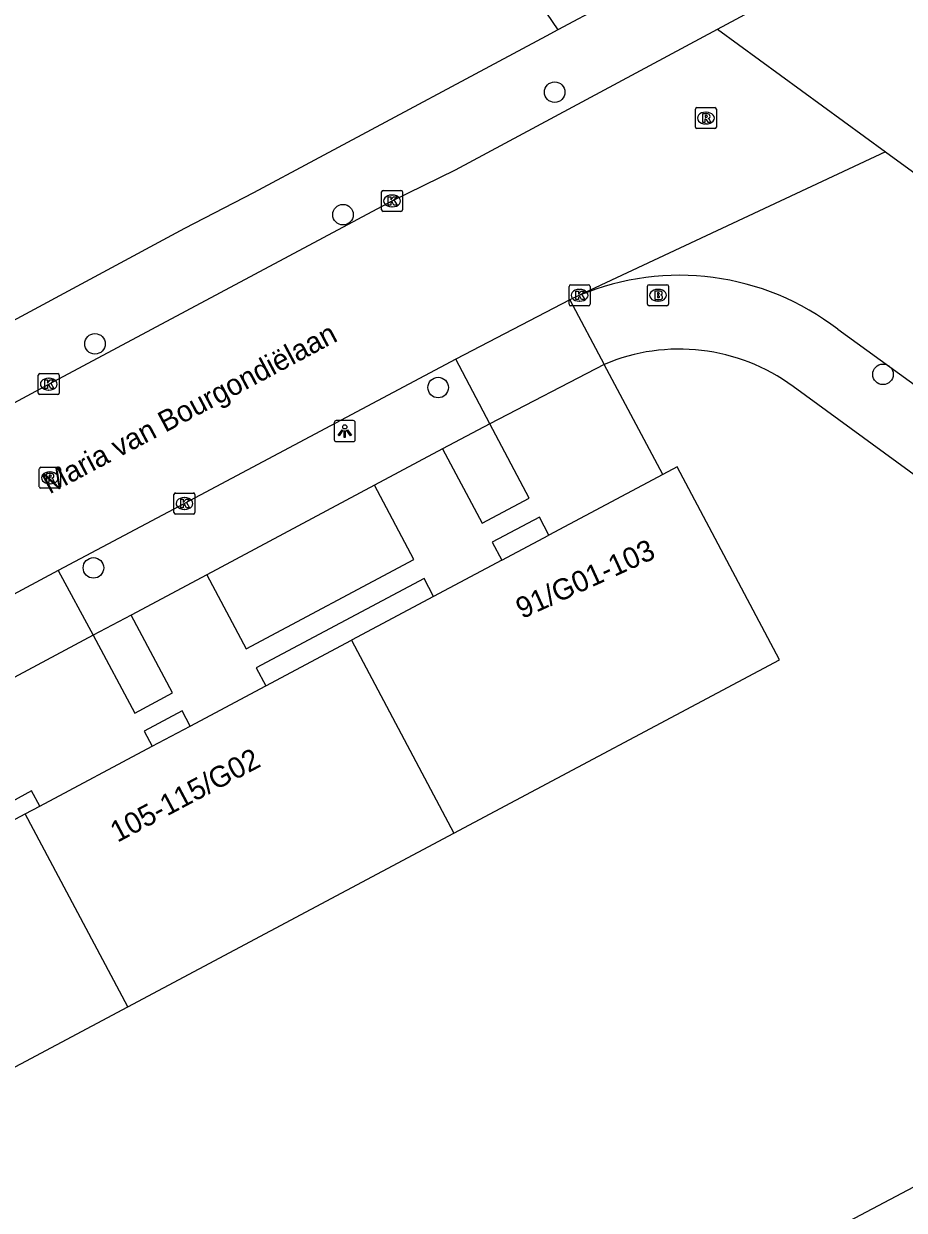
# Model space of a CAD drawing. Extents: x 159675 to 160530, y 382179 to 382901.
# Drawn here: x 159930.6 to 159972.5, y 382360.9 to 382417.3 of the extents above; entities that cross this region are included whole.
import ezdxf

# ---------------------------------------------------------------- set-up
doc = ezdxf.new("R2010")
doc.units = 0
for name, color, linetype in [('IMGEO_Boom', 7, 'Continuous'), ('IMGEO_Brandkraan', 7, 'Continuous'), ('IMGEO_Kolk', 7, 'Continuous'), ('IMGEO_Lichtpunt', 7, 'Continuous'), ('IMGEO_Openbare_ruimte_label', 7, 'Continuous'), ('IMGEO_Pand', 7, 'Continuous'), ('IMGEO_Pand_nummerreeks', 7, 'Continuous'), ('IMGEO_Rijbaan_lokaal_gesloten', 7, 'Continuous'), ('IMGEO_Rijbaan_lokaal_open', 7, 'Continuous'), ('IMGEO_Rioolput', 7, 'Continuous'), ('IMGEO_Voetpad_open', 7, 'Continuous')]:
    doc.layers.add(name, color=color, linetype=linetype)

msp = doc.modelspace()

# ---------------------------------------------------------------- linework, layer by layer
at = {"layer": 'IMGEO_Boom'}
for centre in [(159955.841, 382414.081), (159945.764, 382408.25), (159933.952, 382402.106), (159971.473, 382400.653), (159950.292, 382400.025), (159933.879, 382391.445)]:
    msp.add_circle(centre, 0.489, dxfattribs=at)
at = {"layer": 'IMGEO_Brandkraan'}
for p, q in [((159960.261, 382403.991), (159960.261, 382404.843)), ((159960.336, 382404.917), (159961.188, 382404.917)), ((159960.749, 382404.697), (159960.774, 382404.697)), ((159961.262, 382404.843), (159961.262, 382403.991)), ((159961.188, 382403.917), (159960.336, 382403.917)), ((159960.772, 382404.137), (159960.747, 382404.137))]:
    msp.add_line(p, q, dxfattribs=at)
for points in [[(159960.261, 382403.991), (159960.261, 382404.843)], [(159960.336, 382404.917), (159961.188, 382404.917)], [(159960.609, 382404.617), (159960.609, 382404.217), (159960.822, 382404.217)], [(159960.84, 382404.617), (159960.609, 382404.617)], [(159960.788, 382404.536), (159960.734, 382404.536), (159960.734, 382404.46)], [(159960.734, 382404.46), (159960.787, 382404.46)], [(159961.262, 382404.843), (159961.262, 382403.991)], [(159961.188, 382403.917), (159960.336, 382403.917)], [(159960.796, 382404.384), (159960.734, 382404.384), (159960.734, 382404.303)], [(159960.734, 382404.303), (159960.796, 382404.303)]]:
    msp.add_lwpolyline(points, dxfattribs=at)
for centre, radius, start, end in [((159960.338, 382404.841), 0.0765, 91.552, 178.448), ((159960.338, 382404.841), 0.0765, 91.552, 178.448), ((159960.789, 382404.498), 0.0379, 267.8285, 90.9355), ((159960.844, 382404.472), 0.145, 59.4692, 91.5367), ((159960.869, 382404.519), 0.0922, 285.5137, 58.1501), ((159961.186, 382404.841), 0.0765, 1.552, 88.448), ((159961.186, 382404.841), 0.0765, 1.552, 88.448), ((159960.338, 382403.993), 0.0765, 181.552, 268.448), ((159960.338, 382403.993), 0.0765, 181.552, 268.448), ((159960.797, 382404.343), 0.0404, 269.8759, 90.5077), ((159960.828, 382404.468), 0.251, 268.6676, 293.5347), ((159960.874, 382404.327), 0.105, 301.3115, 78.989), ((159961.186, 382403.993), 0.0765, 271.552, 358.448), ((159961.186, 382403.993), 0.0765, 271.552, 358.448)]:
    msp.add_arc(centre, radius, start, end, dxfattribs=at)
for centre, major_axis, ratio, start_param, end_param in [((159960.748, 382404.417), (-0.387, 0.002), 0.722429, 4.712389, 7.853982), ((159960.773, 382404.417), (-0.39, 0.002), 0.717154, 1.570796, 4.712389)]:
    msp.add_ellipse(centre, major_axis=major_axis, ratio=ratio, start_param=start_param, end_param=end_param, dxfattribs=at)
at = {"layer": 'IMGEO_Kolk'}
for p, q in [((159947.596, 382408.48), (159947.596, 382409.332)), ((159947.671, 382409.406), (159948.523, 382409.406)), ((159948.084, 382409.186), (159948.109, 382409.186)), ((159948.597, 382409.332), (159948.597, 382408.48)), ((159948.523, 382408.406), (159947.671, 382408.406)), ((159948.107, 382408.626), (159948.082, 382408.626)), ((159956.526, 382403.988), (159956.526, 382404.84)), ((159956.601, 382404.914), (159957.453, 382404.914)), ((159957.014, 382404.694), (159957.039, 382404.694)), ((159957.527, 382404.84), (159957.527, 382403.988)), ((159957.453, 382403.914), (159956.601, 382403.914)), ((159957.037, 382404.134), (159957.012, 382404.134)), ((159931.251, 382399.761), (159931.251, 382400.613)), ((159931.326, 382400.687), (159932.178, 382400.687)), ((159932.252, 382400.613), (159932.252, 382399.761)), ((159931.739, 382400.467), (159931.764, 382400.467)), ((159932.178, 382399.687), (159931.326, 382399.687)), ((159931.762, 382399.907), (159931.737, 382399.907)), ((159937.713, 382394.081), (159937.713, 382394.933)), ((159937.788, 382395.007), (159938.64, 382395.007)), ((159938.714, 382394.933), (159938.714, 382394.081)), ((159938.201, 382394.787), (159938.226, 382394.787)), ((159938.64, 382394.007), (159937.788, 382394.007)), ((159938.224, 382394.227), (159938.199, 382394.227))]:
    msp.add_line(p, q, dxfattribs=at)
for points in [[(159947.596, 382408.48), (159947.596, 382409.332)], [(159947.671, 382409.406), (159948.523, 382409.406)], [(159947.917, 382409.106), (159948.04, 382409.106), (159948.04, 382408.955), (159948.17, 382409.106), (159948.334, 382409.106), (159948.188, 382408.955), (159948.341, 382408.706), (159948.189, 382408.706), (159948.104, 382408.87), (159948.04, 382408.803), (159948.04, 382408.706), (159947.917, 382408.706), (159947.917, 382409.106)], [(159948.597, 382409.332), (159948.597, 382408.48)], [(159948.523, 382408.406), (159947.671, 382408.406)], [(159956.526, 382403.988), (159956.526, 382404.84)], [(159956.601, 382404.914), (159957.453, 382404.914)], [(159956.847, 382404.614), (159956.97, 382404.614), (159956.97, 382404.463), (159957.1, 382404.614), (159957.264, 382404.614), (159957.118, 382404.463), (159957.271, 382404.214), (159957.119, 382404.214), (159957.034, 382404.378), (159956.97, 382404.311), (159956.97, 382404.214), (159956.847, 382404.214), (159956.847, 382404.614)], [(159957.527, 382404.84), (159957.527, 382403.988)], [(159957.453, 382403.914), (159956.601, 382403.914)], [(159931.251, 382399.761), (159931.251, 382400.613)], [(159931.326, 382400.687), (159932.178, 382400.687)], [(159932.252, 382400.613), (159932.252, 382399.761)], [(159931.572, 382400.387), (159931.695, 382400.387), (159931.695, 382400.236), (159931.825, 382400.387), (159931.989, 382400.387), (159931.843, 382400.236), (159931.996, 382399.987), (159931.844, 382399.987), (159931.759, 382400.151), (159931.695, 382400.084), (159931.695, 382399.987), (159931.572, 382399.987), (159931.572, 382400.387)], [(159932.178, 382399.687), (159931.326, 382399.687)], [(159937.713, 382394.081), (159937.713, 382394.933)], [(159937.788, 382395.007), (159938.64, 382395.007)], [(159938.714, 382394.933), (159938.714, 382394.081)], [(159938.034, 382394.707), (159938.157, 382394.707), (159938.157, 382394.556), (159938.287, 382394.707), (159938.451, 382394.707), (159938.305, 382394.556), (159938.458, 382394.307), (159938.306, 382394.307), (159938.221, 382394.471), (159938.157, 382394.404), (159938.157, 382394.307), (159938.034, 382394.307), (159938.034, 382394.707)], [(159938.64, 382394.007), (159937.788, 382394.007)]]:
    msp.add_lwpolyline(points, dxfattribs=at)
for centre, start, end in [((159947.673, 382409.33), 91.552, 178.448), ((159947.673, 382409.33), 91.552, 178.448), ((159948.521, 382409.33), 1.552, 88.448), ((159948.521, 382409.33), 1.552, 88.448), ((159947.673, 382408.482), 181.552, 268.448), ((159947.673, 382408.482), 181.552, 268.448), ((159948.521, 382408.482), 271.552, 358.448), ((159948.521, 382408.482), 271.552, 358.448), ((159956.603, 382404.838), 91.552, 178.448), ((159956.603, 382404.838), 91.552, 178.448), ((159957.451, 382404.838), 1.552, 88.448), ((159957.451, 382404.838), 1.552, 88.448), ((159956.603, 382403.99), 181.552, 268.448), ((159956.603, 382403.99), 181.552, 268.448), ((159957.451, 382403.99), 271.552, 358.448), ((159957.451, 382403.99), 271.552, 358.448), ((159931.328, 382400.611), 91.552, 178.448), ((159931.328, 382400.611), 91.552, 178.448), ((159932.176, 382400.611), 1.552, 88.448), ((159932.176, 382400.611), 1.552, 88.448), ((159931.328, 382399.763), 181.552, 268.448), ((159931.328, 382399.763), 181.552, 268.448), ((159932.176, 382399.763), 271.552, 358.448), ((159932.176, 382399.763), 271.552, 358.448), ((159937.79, 382394.931), 91.552, 178.448), ((159937.79, 382394.931), 91.552, 178.448), ((159938.638, 382394.931), 1.552, 88.448), ((159938.638, 382394.931), 1.552, 88.448), ((159937.79, 382394.083), 181.552, 268.448), ((159937.79, 382394.083), 181.552, 268.448), ((159938.638, 382394.083), 271.552, 358.448), ((159938.638, 382394.083), 271.552, 358.448)]:
    msp.add_arc(centre, 0.0765, start, end, dxfattribs=at)
for centre, major_axis, ratio, start_param, end_param in [((159948.083, 382408.906), (-0.387, 0.002), 0.722429, 4.712389, 7.853982), ((159948.108, 382408.906), (-0.39, 0.002), 0.717154, 1.570796, 4.712389), ((159957.013, 382404.414), (-0.387, 0.002), 0.722429, 4.712389, 7.853982), ((159957.038, 382404.414), (-0.39, 0.002), 0.717154, 1.570796, 4.712389), ((159931.738, 382400.187), (-0.387, 0.002), 0.722429, 4.712389, 7.853982), ((159931.763, 382400.187), (-0.39, 0.002), 0.717154, 1.570796, 4.712389), ((159938.2, 382394.507), (-0.387, 0.002), 0.722429, 4.712389, 7.853982), ((159938.225, 382394.507), (-0.39, 0.002), 0.717154, 1.570796, 4.712389)]:
    msp.add_ellipse(centre, major_axis=major_axis, ratio=ratio, start_param=start_param, end_param=end_param, dxfattribs=at)
at = {"layer": 'IMGEO_Lichtpunt'}
for p, q in [((159945.348, 382398.355), (159945.348, 382397.548)), ((159945.348, 382398.355), (159945.348, 382397.548)), ((159946.25, 382398.45), (159945.442, 382398.45)), ((159946.25, 382398.45), (159945.442, 382398.45)), ((159946.344, 382397.548), (159946.344, 382398.355)), ((159946.344, 382397.548), (159946.344, 382398.355)), ((159945.442, 382397.454), (159946.25, 382397.454)), ((159945.442, 382397.454), (159946.25, 382397.454))]:
    msp.add_line(p, q, dxfattribs=at)
for points in [[(159945.722, 382398.019), (159945.761, 382397.991), (159945.573, 382397.729), (159945.535, 382397.756), (159945.722, 382398.019)], [(159945.824, 382397.971), (159945.871, 382397.971), (159945.871, 382397.649), (159945.824, 382397.649), (159945.824, 382397.971)], [(159945.934, 382397.991), (159945.972, 382398.018), (159946.159, 382397.756), (159946.12, 382397.728), (159945.934, 382397.991)]]:
    msp.add_lwpolyline(points, dxfattribs=at)
msp.add_circle((159945.847, 382398.153), 0.0994, dxfattribs=at)
for centre, start, end in [((159945.442, 382398.355), 90, 180), ((159945.442, 382398.355), 90, 180), ((159946.25, 382398.355), 0, 90), ((159946.25, 382398.355), 0, 90), ((159945.442, 382397.548), 180, 270), ((159945.442, 382397.548), 180, 270), ((159946.25, 382397.548), 270, 0), ((159946.25, 382397.548), 270, 360)]:
    msp.add_arc(centre, 0.0946, start, end, dxfattribs=at)
at = {"layer": 'IMGEO_Pand'}
for points in [[(159951.046, 382378.827), (159966.549, 382387.076), (159961.672, 382396.257), (159960.984, 382395.891)], [(159960.984, 382395.891), (159955.567, 382393.008)], [(159953.319, 382391.812), (159955.567, 382393.008)], [(159953.319, 382391.812), (159950.075, 382390.086)], [(159950.075, 382390.086), (159946.172, 382388.009)], [(159942.087, 382385.835), (159946.172, 382388.009)], [(159946.172, 382388.009), (159951.046, 382378.827)], [(159938.488, 382383.92), (159942.087, 382385.835)], [(159936.682, 382382.959), (159938.488, 382383.92)], [(159931.319, 382380.106), (159936.682, 382382.959)], [(159929.706, 382379.247), (159930.634, 382379.741)], [(159930.634, 382379.741), (159931.319, 382380.106)], [(159935.509, 382370.559), (159930.634, 382379.741)], [(159935.509, 382370.559), (159951.046, 382378.827)], [(159919.971, 382362.292), (159935.509, 382370.559)]]:
    msp.add_lwpolyline(points, dxfattribs=at)
at = {"layer": 'IMGEO_Rijbaan_lokaal_gesloten'}
for points in [[(159906.798, 382386.87), (159914.495, 382390.981), (159915.606, 382391.545), (159926.173, 382397.188), (159931.751, 382400.186), (159948.098, 382408.904), (159951.117, 382410.379), (159963.588, 382417.082)], [(159963.588, 382417.082), (159971.594, 382411.249)], [(159971.594, 382411.249), (159957.027, 382404.415)], [(159971.594, 382411.249), (159976.539, 382407.646)], [(159956.561, 382404.202), (159951.131, 382401.378)], [(159957.027, 382404.415), (159956.561, 382404.202)], [(159969.32, 382402.798), (159992.637, 382385.919), (159992.936, 382385.697)], [(159951.131, 382401.378), (159938.214, 382394.508), (159932.202, 382391.318)], [(159932.202, 382391.318), (159926.838, 382388.444)]]:
    msp.add_lwpolyline(points, dxfattribs=at)
msp.add_arc((159961.781, 382393.016), 12.35, 52.3754, 112.6374, dxfattribs=at)
at = {"layer": 'IMGEO_Rijbaan_lokaal_open'}
for points in [[(159953.124, 382421.28), (159955.991, 382417.045)], [(159961.663, 382420.078), (159960.402, 382419.404), (159955.991, 382417.045)], [(159963.588, 382417.082), (159967.119, 382418.98)], [(159959.456, 382354.877), (159977.713, 382364.513)]]:
    msp.add_lwpolyline(points, dxfattribs=at)
at = {"layer": 'IMGEO_Rioolput'}
for p, q in [((159962.543, 382412.42), (159962.543, 382413.272)), ((159962.618, 382413.346), (159963.47, 382413.346)), ((159963.031, 382413.126), (159963.056, 382413.126)), ((159963.544, 382413.272), (159963.544, 382412.42)), ((159963.054, 382412.566), (159963.029, 382412.566)), ((159963.47, 382412.346), (159962.618, 382412.346)), ((159931.302, 382395.304), (159931.302, 382396.156)), ((159931.377, 382396.23), (159932.229, 382396.23)), ((159931.79, 382396.01), (159931.815, 382396.01)), ((159932.303, 382396.156), (159932.303, 382395.304)), ((159931.813, 382395.45), (159931.788, 382395.45)), ((159932.229, 382395.23), (159931.377, 382395.23))]:
    msp.add_line(p, q, dxfattribs=at)
for points in [[(159962.543, 382412.42), (159962.543, 382413.272)], [(159962.618, 382413.346), (159963.47, 382413.346)], [(159963.132, 382413.044), (159962.88, 382413.046), (159962.88, 382412.646)], [(159963.058, 382412.965), (159963.004, 382412.965), (159963.004, 382412.884)], [(159963.544, 382413.272), (159963.544, 382412.42)], [(159962.88, 382412.646), (159963.004, 382412.646), (159963.004, 382412.808), (159963.015, 382412.808)], [(159963.004, 382412.884), (159963.056, 382412.884)], [(159963.062, 382412.779), (159963.133, 382412.646), (159963.273, 382412.646), (159963.208, 382412.772)], [(159963.47, 382412.346), (159962.618, 382412.346)], [(159931.302, 382395.304), (159931.302, 382396.156)], [(159931.377, 382396.23), (159932.229, 382396.23)], [(159932.303, 382396.156), (159932.303, 382395.304)], [(159931.891, 382395.928), (159931.639, 382395.93), (159931.639, 382395.53)], [(159931.639, 382395.53), (159931.763, 382395.53), (159931.763, 382395.692), (159931.774, 382395.692)], [(159931.817, 382395.849), (159931.763, 382395.849), (159931.763, 382395.768)], [(159931.763, 382395.768), (159931.815, 382395.768)], [(159931.821, 382395.663), (159931.892, 382395.53), (159932.032, 382395.53), (159931.967, 382395.656)], [(159932.229, 382395.23), (159931.377, 382395.23)]]:
    msp.add_lwpolyline(points, dxfattribs=at)
for centre, radius, start, end in [((159962.62, 382413.27), 0.0765, 91.552, 178.448), ((159962.62, 382413.27), 0.0765, 91.552, 178.448), ((159963.064, 382412.869), 0.0964, 77.0061, 93.1865), ((159963.078, 382412.926), 0.0378, 276.6634, 79.6772), ((159963.131, 382412.934), 0.109, 350.3612, 89.416), ((159963.468, 382413.27), 0.0765, 1.552, 88.448), ((159963.468, 382413.27), 0.0765, 1.552, 88.448), ((159962.62, 382412.422), 0.0765, 181.552, 268.448), ((159962.62, 382412.422), 0.0765, 181.552, 268.448), ((159963.014, 382412.755), 0.0533, 26.0293, 88.6989), ((159963.04, 382413.073), 0.19, 274.7715, 282.9687), ((159963.129, 382412.934), 0.112, 277.5842, 350.9817), ((159963.113, 382412.719), 0.108, 29.5134, 73.7905), ((159963.468, 382412.422), 0.0765, 271.552, 358.448), ((159963.468, 382412.422), 0.0765, 271.552, 358.448), ((159931.379, 382396.154), 0.0765, 91.552, 178.448), ((159931.379, 382396.154), 0.0765, 91.552, 178.448), ((159932.227, 382396.154), 0.0765, 1.552, 88.448), ((159932.227, 382396.154), 0.0765, 1.552, 88.448), ((159931.773, 382395.639), 0.0533, 26.0293, 88.6989), ((159931.799, 382395.957), 0.19, 274.7715, 282.9687), ((159931.823, 382395.753), 0.0964, 77.0061, 93.1865), ((159931.837, 382395.81), 0.0378, 276.6634, 79.6772), ((159931.89, 382395.818), 0.109, 350.3612, 89.416), ((159931.888, 382395.818), 0.112, 277.5842, 350.9817), ((159931.872, 382395.603), 0.108, 29.5134, 73.7905), ((159931.379, 382395.306), 0.0765, 181.552, 268.448), ((159931.379, 382395.306), 0.0765, 181.552, 268.448), ((159932.227, 382395.306), 0.0765, 271.552, 358.448), ((159932.227, 382395.306), 0.0765, 271.552, 358.448)]:
    msp.add_arc(centre, radius, start, end, dxfattribs=at)
for centre, major_axis, ratio, start_param, end_param in [((159963.03, 382412.846), (-0.387, 0.002), 0.722429, 4.712389, 7.853982), ((159963.055, 382412.846), (-0.39, 0.002), 0.717154, 1.570796, 4.712389), ((159931.789, 382395.73), (-0.387, 0.002), 0.722429, 4.712389, 7.853982), ((159931.814, 382395.73), (-0.39, 0.002), 0.717154, 1.570796, 4.712389)]:
    msp.add_ellipse(centre, major_axis=major_axis, ratio=ratio, start_param=start_param, end_param=end_param, dxfattribs=at)
at = {"layer": 'IMGEO_Voetpad_open'}
for points in [[(159955.991, 382417.045), (159955.44, 382416.75), (159944.408, 382410.851), (159941.502, 382409.297), (159938.215, 382407.586), (159929.814, 382403.078)], [(159956.561, 382404.202), (159958.199, 382401.124)], [(159952.751, 382398.301), (159951.131, 382401.378)], [(159958.199, 382401.124), (159952.751, 382398.301)], [(159960.984, 382395.891), (159958.199, 382401.124)], [(159995.228, 382379.629), (159967.191, 382400.081)], [(159952.751, 382398.301), (159950.504, 382397.103)], [(159950.504, 382397.103), (159952.383, 382393.571), (159954.631, 382394.768), (159952.751, 382398.301)], [(159950.504, 382397.103), (159947.26, 382395.375)], [(159947.26, 382395.375), (159939.275, 382391.119)], [(159939.275, 382391.119), (159941.151, 382387.594), (159949.139, 382391.845), (159947.26, 382395.375)], [(159955.567, 382393.008), (159955.113, 382393.862), (159952.865, 382392.666), (159953.319, 382391.812)], [(159932.202, 382391.318), (159933.872, 382388.24)], [(159939.275, 382391.119), (159935.677, 382389.202)], [(159950.075, 382390.086), (159949.62, 382390.939), (159941.633, 382386.689), (159942.087, 382385.835)], [(159935.677, 382389.202), (159933.872, 382388.24)], [(159933.872, 382388.24), (159935.846, 382384.531), (159937.651, 382385.492), (159935.677, 382389.202)], [(159933.872, 382388.24), (159928.509, 382385.387)], [(159938.488, 382383.92), (159938.103, 382384.643), (159936.297, 382383.682), (159936.682, 382382.959)], [(159931.319, 382380.106), (159930.935, 382380.828), (159929.322, 382379.97), (159929.706, 382379.247)]]:
    msp.add_lwpolyline(points, dxfattribs=at)
msp.add_arc((159961.779, 382392.708), 9.146, 53.7219, 113.0455, dxfattribs=at)

# ---------------------------------------------------------------- texts
at = {"layer": 'IMGEO_Openbare_ruimte_label'}
msp.add_text('Maria van Bourgondiëlaan', height=1, rotation=28.0253, dxfattribs=at).set_placement((159931.787, 382394.934))
at = {"layer": 'IMGEO_Pand_nummerreeks'}
for s, rotation, p in [('91/G01-103', 24.5684, (159954.288, 382389)), ('105-115/G02', 28.0176, (159935.022, 382378.36))]:
    msp.add_text(s, height=1, rotation=rotation, dxfattribs=at).set_placement(p)

doc.saveas('drawing.dxf')
